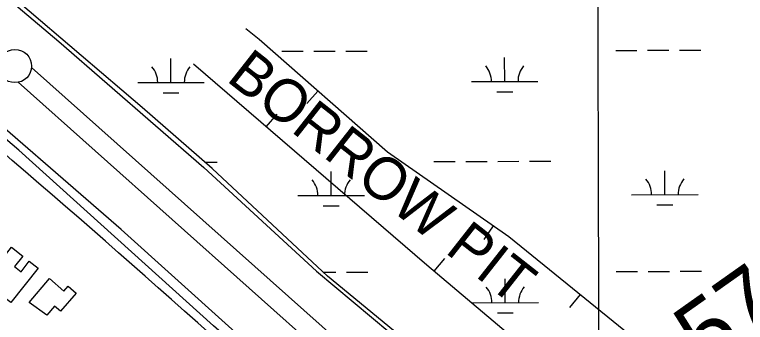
# Model space of a CAD drawing. Extents: x 3355724 to 3393621, y 594744 to 620174.
# Drawn here: x 3374730 to 3375830, y 615735 to 616199 of the extents above; entities that cross this region are included whole.
import ezdxf

# ---------------------------------------------------------------- set-up
doc = ezdxf.new("R2010")
doc.units = 0
for name, color, linetype in [('V-BLDG-OTLN', 7, 'Continuous'), ('V-BORW-IDEN', 7, 'Continuous'), ('V-BORW-LINE', 7, 'Continuous'), ('V-GRID-MAJR', 7, 'Continuous'), ('V-LEVE-TOET', 7, 'Continuous'), ('V-RIVR-EDGE', 7, 'Continuous'), ('V-ROAD-CNTR', 7, 'Continuous'), ('V-SURV-IDEN', 7, 'Continuous'), ('V-SURV-LINE', 7, 'Continuous'), ('V-TOPO-SHOR', 7, 'Continuous'), ('V-WETL-SWMP', 7, 'Continuous')]:
    doc.layers.add(name, color=color, linetype=linetype)

msp = doc.modelspace()

# ---------------------------------------------------------------- linework, layer by layer
at = {"layer": 'V-BLDG-OTLN'}
for points in [[(3374683.944, 615795.539), (3374725.869, 615848.711), (3374742.861, 615835.313), (3374730.401, 615819.511), (3374740.219, 615811.769), (3374752.575, 615827.439), (3374765.8310000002, 615816.986), (3374725, 615765.2000000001)], [(3374752.251, 615765.368), (3374783.188, 615801.282), (3374804.764, 615782.696), (3374811.002, 615789.942), (3374822.9250000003, 615779.671), (3374799.304, 615752.248), (3374790.313, 615759.9940000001), (3374778.7600000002, 615746.582)]]:
    msp.add_lwpolyline(points, close=True, dxfattribs=at)
at = {"layer": 'V-BORW-LINE'}
for p, q in [((3375186.619, 616083.447), (3375170.1180000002, 616064.666)), ((3375108.887, 616029.9379999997), (3375125.201, 616048.8809999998)), ((3375450.373, 615880.6759999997), (3375436.08, 615860.1649999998)), ((3375361.453, 615812.6079999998), (3375377.5840000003, 615831.7079999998)), ((3375580.949, 615777.3129999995), (3375565.188, 615757.9069999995))]:
    msp.add_line(p, q, dxfattribs=at)
msp.add_lwpolyline([(3374999.289, 616124.3249999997), (3375350.466, 615821.8869999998), (3375623.964, 615590.9099999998), (3375947.058, 615275.3879999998), (3376212.667, 615040.2929999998), (3376456.716, 614821.7659999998), (3376730.359, 614537.2219999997), (3376919.627, 614374.7149999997), (3376985.098, 614331.7339999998), (3377039.049, 614329.4969999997), (3377044.183, 614367.4619999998), (3376929.0330000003, 614512.7299999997), (3376763.9420000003, 614658.5999999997), (3376650.372, 614798.0959999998), (3376365.971, 615066.9819999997), (3376116.19, 615339.8889999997), (3375874.953, 615560.1719999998), (3375665.458, 615708.6739999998), (3375473.693, 615864.4269999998), (3375291.071, 615991.6769999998), (3375098.1550000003, 616161.1709999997), (3375078.477, 616177.2309999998)], dxfattribs=at)
at = {"layer": 'V-GRID-MAJR'}
msp.add_spline([(3375649.97, 600169.845), (3375634.111, 606227.569), (3375618.242, 612288.761), (3375602.373, 618349.974), (3375602.364, 618353.419)], degree=3, dxfattribs=at)
at = {"layer": 'V-LEVE-TOET'}
for points in [[(3375825.827, 615008.099), (3375822.0300000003, 615015.069), (3375811.421, 615025.452), (3375795.215, 615044.861), (3375673.98, 615158.795), (3375432.599, 615386.572), (3375213.561, 615584.466), (3374890.5870000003, 615875.407), (3374635.994, 616096.192), (3374322.151, 616352.343), (3373944.17, 616649.422), (3373708.889, 616836.304), (3373573.176, 616934.682), (3373207.762, 617215.082), (3372868.8510000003, 617474.657), (3372670.815, 617620.3910000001), (3372460.949, 617765.402), (3372217.63, 617927.042), (3371905.281, 618137.949), (3371607.651, 618305.732), (3371539.629639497, 618342.7830789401)], [(3374580.719, 616340.588), (3374797.119, 616158.1190000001), (3375014.911, 615968.7710000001), (3375184.477, 615812.333), (3375294.744, 615720.412), (3375421.562, 615609.273), (3375501.508, 615540.672), (3375591.798, 615461.088), (3375653.836, 615403.451), (3375709.619, 615348.512), (3375771.0100000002, 615272.302), (3375892.346, 615152.893)]]:
    msp.add_lwpolyline(points, dxfattribs=at)
at = {"layer": 'V-RIVR-EDGE'}
msp.add_spline([(3375380.8204065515, 618352.839487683), (3375420.269161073, 618323.7288901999), (3375445.0711899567, 618301.3690852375), (3375471.3372128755, 618279.7367578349), (3375501.2514702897, 618255.1710190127), (3375536.276148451, 618227.6682532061), (3375549.0314108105, 618211.9181147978), (3375559.9806337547, 618204.9456133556), (3375576.404016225, 618194.3040879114), (3375599.7519938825, 618175.2378175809), (3375638.7805102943, 618140.7797242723), (3375656.2815507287, 618122.4590093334), (3375673.4188523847, 618104.8702914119), (3375771.5203854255, 618011.4127710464), (3375800.3352914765, 617985.7531042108), (3375821.847401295, 617963.4014342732), (3375844.090604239, 617941.047956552), (3375861.608818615, 617929.6726263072), (3375882.3952586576, 617909.5160435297), (3375904.2557410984, 617880.2180850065), (3375960.4324058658, 617832.5578325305), (3375992.1536065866, 617799.5800033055), (3376041.0103011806, 617748.2823630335), (3376074.5510996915, 617712.0100952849), (3376185.4087989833, 617603.1679830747), (3376226.9789673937, 617561.7581778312), (3376338.574990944, 617455.8386303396), (3376381.9665649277, 617411.8654796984), (3376437.399482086, 617359.0893831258), (3376479.6935124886, 617314.7533975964), (3376500.101751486, 617289.4800668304), (3376531.4610212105, 617257.9653277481), (3376571.5708111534, 617217.2902311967), (3376620.047496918, 617160.1447498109), (3376637.9023333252, 617137.0710256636), (3376661.24307985, 617115.0803828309), (3376679.4806367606, 617098.9511394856), (3376697.7100586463, 617079.5319770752), (3376717.0316007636, 617058.2823701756), (3376731.600133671, 617036.6789673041), (3376745.4574590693, 617023.1193965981), (3376758.9483340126, 617009.1951832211), (3376794.6742768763, 616969.6275730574), (3376867.204724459, 616883.1787097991), (3376881.7859118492, 616866.6929588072), (3376901.8349315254, 616843.979357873), (3376931.3782190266, 616817.221243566), (3376968.555501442, 616773.2634590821), (3377038.169711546, 616690.1117460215), (3377066.9556930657, 616652.7545891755), (3377087.743037, 616632.9635529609), (3377103.0607408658, 616618.669273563), (3377120.9173850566, 616596.3266425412), (3377186.5087751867, 616512.4537791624), (3377216.026753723, 616475.460361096), (3377255.388276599, 616427.841687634), (3377303.854115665, 616366.3096474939), (3377369.4599680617, 616288.2855291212), (3377405.909772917, 616245.7917386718), (3377491.5239698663, 616128.6044240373), (3377526.120732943, 616075.8798492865), (3377552.7197623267, 616041.08694173), (3377626.701549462, 615950.2479041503), (3377654.399026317, 615916.1833780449), (3377678.450980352, 615886.1489030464), (3377699.9468201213, 615857.2173949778), (3377777.9152715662, 615752.4776452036), (3377803.0647691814, 615722.8060050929), (3377843.5301628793, 615678.1089924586), (3377867.953086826, 615650.2668929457), (3377881.43311507, 615631.9561208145), (3377905.4760301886, 615598.2661801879), (3377926.597284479, 615565.6801103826), (3377940.798463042, 615543.3465182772), (3377958.6496838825, 615518.8106078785), (3377971.761453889, 615499.4040999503), (3377982.683560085, 615481.4652016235), (3378059.551756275, 615375.2659772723), (3378094.520393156, 615325.0993245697), (3378126.935627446, 615277.1322784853), (3378185.172699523, 615175.7312579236), (3378207.005161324, 615135.1013559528), (3378307.8963870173, 614987.1701665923), (3378349.410514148, 614923.0964744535), (3378390.937295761, 614864.1404341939), (3378419.7223733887, 614826.4177307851), (3378449.2403519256, 614789.4243127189), (3378467.069879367, 614756.1152848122), (3378482.3496197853, 614726.4680497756), (3378509.64900998, 614679.2447512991), (3378546.0599474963, 614621.032458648), (3378577.3622720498, 614566.4882861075), (3378597.7298359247, 614524.765360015), (3378622.461361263, 614473.892923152), (3378650.120874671, 614424.4754414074), (3378694.902323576, 614351.2549501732), (3378714.9079564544, 614310.995114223), (3378749.113864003, 614248.0361396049), (3378759.6767508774, 614232.6569711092), (3378776.7914552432, 614205.9295891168), (3378791.6975140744, 614172.9933389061), (3378807.6947892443, 614137.8610976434), (3378844.8051836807, 614066.8528675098), (3378863.710561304, 614025.1335569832), (3378885.923935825, 613990.7170426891), (3378900.114267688, 613963.9968918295), (3378916.496071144, 613936.540224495), (3378929.245006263, 613918.2312601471), (3379005.705172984, 613794.8522512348), (3379023.1718655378, 613762.6407669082), (3379028.9934937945, 613751.6599077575), (3379038.0978099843, 613737.7465410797), (3379055.9707242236, 613721.9837481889), (3379063.2581542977, 613712.4614597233), (3379072.707227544, 613690.1396182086), (3379096.6931974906, 613633.4202441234), (3379107.597225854, 613608.1704145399), (3379127.6037626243, 613568.2761251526), (3379150.166413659, 613527.2788688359), (3379171.2840523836, 613493.2306127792), (3379216.0392884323, 613409.4092712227), (3379256.795205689, 613334.3709899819), (3379314.9789481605, 613211.4027222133), (3379346.2424053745, 613141.1400474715), (3379363.682885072, 613098.3277128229), (3379415.7174161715, 613001.6941637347), (3379435.348463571, 612957.7797660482), (3379449.5207176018, 612923.7486839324), (3379470.6184707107, 612881.6584034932), (3379540.480721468, 612750.9847333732), (3379564.8620664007, 612706.32749197), (3379589.606246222, 612660.5727069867), (3379652.216318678, 612553.6776412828), (3379662.3955811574, 612530.9884454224), (3379662.743049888, 612523.6766102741), (3379672.9403902, 612508.2983456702), (3379687.8600074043, 612480.845293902), (3379704.225540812, 612446.808788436), (3379704.944883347, 612442.0548753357), (3379706.0297724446, 612437.3000583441), (3379717.657662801, 612409.1240484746), (3379731.492390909, 612386.4258136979), (3379735.1243553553, 612376.9125641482), (3379746.0365187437, 612354.95265363), (3379762.0699495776, 612334.4422748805), (3379789.381090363, 612291.9710817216), (3379802.843040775, 612266.3493783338), (3379843.9645045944, 612191.3101932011), (3379872.705291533, 612135.6757082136), (3379896.3736211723, 612098.3312058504), (3379901.453309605, 612082.9655957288), (3379906.5013618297, 612054.8058559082), (3379909.405848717, 612046.7566003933), (3379918.87571147, 612032.8423298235), (3379935.2764966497, 612013.0621403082), (3379944.727377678, 611991.4713919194), (3379953.4327033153, 611964.0337063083), (3379958.889688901, 611953.4192976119), (3379967.2791820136, 611946.0875768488), (3379978.563219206, 611926.6855883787), (3379993.4846441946, 611899.963629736), (3380009.5054205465, 611874.3355991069), (3380070.2678745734, 611759.4030284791), (3380080.7991252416, 611731.2297302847), (3380088.0657658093, 611713.2998708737), (3380095.703376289, 611697.5623869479), (3380112.460669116, 611674.1258279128), (3380124.8341148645, 611651.7967552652), (3380123.721205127, 611645.219628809), (3380124.7934397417, 611635.3471599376), (3380137.1605582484, 611610.4592613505), (3380148.81375757, 611592.5185552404), (3380155.016298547, 611587.7510837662), (3380167.036852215, 611570.54056689), (3380177.5780456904, 611546.3882808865), (3380195.7758313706, 611514.1749887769), (3380214.7083257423, 611483.4220751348), (3380224.5346961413, 611465.8514350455), (3380228.1494866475, 611449.3928008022), (3380233.5911060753, 611432.5641005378), (3380253.971324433, 611395.9588263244), (3380276.5195132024, 611349.1128250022), (3380293.9599928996, 611306.3004903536), (3380320.89293264, 611258.7125492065), (3380341.2794782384, 611224.6661009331), (3380352.568938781, 611207.4573918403), (3380364.603954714, 611196.0956199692), (3380367.1419911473, 611187.6817217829), (3380368.9498383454, 611179.6351779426), (3380378.4215088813, 611166.4520004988), (3380388.9952424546, 611155.4593907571), (3380388.981684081, 611149.9761923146), (3380391.1424233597, 611136.8110927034), (3380399.1446765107, 611120.707158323), (3380419.9039998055, 611089.5841786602), (3380436.6793704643, 611073.4585508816), (3380444.3296354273, 611062.8387188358), (3380443.954146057, 611058.8186105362), (3380442.8430441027, 611052.9725772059), (3380446.478624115, 611044.9215139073), (3380459.9568445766, 611025.8796486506), (3380464.3063437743, 611010.8813928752), (3380471.205629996, 610992.2213442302), (3380486.474523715, 610958.1875504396), (3380519.26163181, 610912.7784264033), (3380526.8847800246, 610891.1921974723), (3380537.404280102, 610858.266793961), (3380551.572918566, 610822.7735255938), (3380593.77204035, 610740.0551509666), (3380615.2389555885, 610699.4261528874), (3380640.7386336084, 610663.5393173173), (3380652.3836979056, 610642.3086921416), (3380663.6487533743, 610615.2302258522), (3380668.0009642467, 610601.3286097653), (3380674.1890429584, 610590.712393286), (3380692.0619571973, 610574.9496003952), (3380702.632075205, 610562.4948044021), (3380712.4557339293, 610543.8275246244), (3380727.724627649, 610509.7937308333), (3380735.3468719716, 610487.8419553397), (3380741.1422873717, 610466.2602458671), (3380745.881738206, 610461.1308433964), (3380752.8153723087, 610456.3615641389), (3380760.4656372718, 610445.7417320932), (3380779.7492159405, 610409.1391695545), (3380795.7519144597, 610376.200207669), (3380801.586197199, 610370.337000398), (3380807.424999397, 610366.3015259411), (3380811.785345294, 610355.6898289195), (3380812.48841778, 610344.3560776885), (3380817.937268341, 610330.4517499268), (3380829.2267288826, 610313.2430408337), (3380839.048579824, 610293.8446679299), (3380846.348664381, 610289.4400313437), (3380854.008872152, 610282.8412114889), (3380859.103926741, 610273.6898929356), (3380867.0971409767, 610253.9304929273), (3380868.5484805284, 610249.5403186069), (3380877.662739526, 610239.6479641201), (3380887.12808282, 610223.9059607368), (3380896.594330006, 610208.529503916), (3380899.848997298, 610194.265052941), (3380899.839054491, 610190.2440407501), (3380906.0497304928, 610188.7664883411), (3380912.98607627, 610185.0938487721), (3380918.449389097, 610177.0382660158), (3380918.434926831, 610171.1895210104), (3380918.4186567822, 610164.6096828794), (3380918.4014828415, 610157.6642981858), (3380926.0634983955, 610151.7965714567), (3380935.5405922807, 610140.80667339), (3380947.1838487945, 610118.8449550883), (3380956.2854533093, 610103.8349487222), (3380965.0359735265, 610094.6745912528), (3380973.404677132, 610078.9352995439), (3380975.210716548, 610070.1576625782), (3380981.770669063, 610062.0993681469), (3380992.7144686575, 610052.9335873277), (3380996.7155952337, 610044.8816201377), (3380999.973878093, 610032.0793554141), (3380999.951280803, 610022.9406913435), (3381003.216794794, 610013.0627991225), (3381010.1468133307, 610006.8313336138), (3381018.9063724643, 610001.3264417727), (3381025.8273520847, 609991.4395106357), (3381035.295407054, 609976.7941469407), (3381052.049988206, 609952.2609482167), (3381064.0642146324, 609932.4916054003), (3381081.1689761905, 609901.7432112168), (3381081.1445711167, 609891.8734540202), (3381086.5807671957, 609872.8514743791), (3381093.837464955, 609850.900602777), (3381104.0221507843, 609830.4046862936), (3381125.493585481, 609791.6034210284), (3381152.4418913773, 609750.2297714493), (3381171.0196858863, 609723.8643204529), (3381189.573979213, 609687.9946588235), (3381212.133918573, 609645.9007628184), (3381231.427440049, 609613.3192124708), (3381244.142931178, 609581.4850252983), (3381257.9387919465, 609543.0682883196), (3381275.036322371, 609509.395521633), (3381303.062286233, 609460.3426825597), (3381339.808037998, 609389.7009028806), (3381375.859756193, 609334.0483400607), (3381398.434157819, 609297.8031890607), (3381410.8103152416, 609276.5707561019), (3381420.3027752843, 609271.7951496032), (3381423.218108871, 609268.132452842), (3381426.1262113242, 609261.545383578), (3381429.776253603, 609259.343065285), (3381434.8920976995, 609258.5993176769), (3381439.6387796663, 609256.394287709), (3381499.3398457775, 609155.7207447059), (3381528.0752093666, 609097.8929803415), (3381535.3545044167, 609085.08077281), (3381535.3346188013, 609077.0387484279), (3381535.3056942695, 609065.3412584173), (3381535.287616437, 609058.0303271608), (3381541.1255147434, 609053.6293061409), (3381551.713710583, 609048.4854414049), (3381554.98193625, 609039.7041888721), (3381564.0735979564, 609020.6731703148), (3381586.268894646, 608978.9457247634), (3381604.8258996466, 608944.1727028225), (3381620.107447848, 608915.2565609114), (3381628.486094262, 608903.5382813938), (3381636.8810107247, 608898.3998400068), (3381651.07857372, 608874.60406165), (3381663.082857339, 608850.8137066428), (3381678.3824833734, 608829.2084959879), (3381690.774910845, 608814.5559011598), (3381704.606023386, 608790.3954801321), (3381708.222621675, 608774.6679390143), (3381710.374322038, 608757.8473737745), (3381710.3517247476, 608748.7087097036), (3381708.496875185, 608737.7468322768), (3381708.117770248, 608732.264537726), (3381711.372437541, 608718.000086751), (3381715.707474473, 608697.1530859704), (3381717.882676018, 608689.836731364), (3381723.33785382, 608678.4912295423), (3381733.5315785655, 608661.650778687), (3381741.560948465, 608656.5132411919), (3381747.0342041, 608652.4786706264), (3381752.8721024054, 608648.077649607), (3381759.8174870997, 608648.0604756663), (3381763.4702410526, 608646.9547970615), (3381765.648154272, 608640.7350821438), (3381769.2855420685, 608633.4151119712), (3381776.2137528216, 608626.4525533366), (3381784.6177082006, 608624.9695775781), (3381791.560381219, 608623.8557639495), (3381802.134114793, 608612.8631542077), (3381808.334847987, 608607.3645896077), (3381820.722756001, 608590.8842619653), (3381831.6692672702, 608582.8151208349), (3381840.7826223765, 608572.5572197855), (3381857.5118945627, 608537.7887173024), (3381870.222866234, 608504.1267973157), (3381876.0155699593, 608481.4484481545), (3381884.748012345, 608464.9771594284), (3381898.5872599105, 608444.1066574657), (3381913.540321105, 608430.1788285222), (3381932.090094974, 608392.4814340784), (3381960.8317858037, 608337.2124956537), (3381973.560835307, 608310.8615069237), (3381973.5517963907, 608307.2060412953), (3381972.802625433, 608299.8969178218), (3381972.790874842, 608295.144812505), (3381974.966076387, 608287.8284578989), (3381977.8768905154, 608282.3380283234), (3381985.906260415, 608277.2004908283), (3381990.2774530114, 608270.9753525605), (3381997.1939131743, 608259.2606886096), (3382005.925451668, 608242.4238533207), (3382015.7427831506, 608221.1977476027), (3382031.0261391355, 608193.0126988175), (3382044.491705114, 608168.8531816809), (3382063.0487101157, 608134.0801597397), (3382080.1326821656, 608094.9241946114), (3382096.4936961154, 608059.0599563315), (3382116.8594522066, 608016.6059371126), (3382135.0545262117, 607983.2960053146), (3382154.3344893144, 607945.231256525), (3382180.5173542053, 607889.9686453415), (3382186.330847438, 607875.6978671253), (3382201.587990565, 607836.9119680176), (3382211.0036198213, 607801.0649036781), (3382218.988699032, 607778.0155846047), (3382226.2725135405, 607767.0311098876), (3382233.5581358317, 607756.777728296), (3382247.730389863, 607722.7466461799), (3382259.0017725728, 607698.22700583), (3382261.536193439, 607688.3509213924), (3382266.620401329, 607674.813044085), (3382270.996113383, 607670.4156386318), (3382277.9143813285, 607659.4320678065), (3382286.289412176, 607646.2516020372), (3382288.8247369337, 607636.7410641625), (3382293.537974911, 607621.0108113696), (3382300.433645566, 607600.8885764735), (3382310.614715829, 607578.9304737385), (3382319.7208398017, 607565.7482001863), (3382337.926760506, 607536.8248271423), (3382350.3047257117, 607516.3234873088), (3382357.5731740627, 607499.1247210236), (3382366.3038086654, 607481.9223391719), (3382374.3151007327, 607469.47387042), (3382380.8813804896, 607463.9744019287), (3382386.728317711, 607463.2288465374), (3382390.7493299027, 607463.2189037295), (3382394.3966605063, 607459.9199457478), (3382404.9459890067, 607439.05757881), (3382412.575464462, 607420.0301758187), (3382419.0947418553, 607395.5222860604), (3382431.8147524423, 607365.5158317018), (3382444.5383785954, 607336.9715635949), (3382461.276689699, 607305.8585267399), (3382481.643349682, 607263.7700540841), (3382528.251627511, 607190.1794968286), (3382546.8239986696, 607161.6207664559), (3382558.102612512, 607140.0254986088), (3382565.367445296, 607121.3645460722), (3382577.7408910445, 607099.0354734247), (3382593.75262848, 607069.7519771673), (3382609.407858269, 607044.1248504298), (3382624.339226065, 607021.4239039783), (3382632.3559414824, 607011.1687146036), (3382645.4830776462, 606997.9764982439), (3382659.346730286, 606986.9757534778), (3382671.3745150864, 606972.6896091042), (3382685.2137626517, 606951.8191071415)], degree=3, dxfattribs=at)
at = {"layer": 'V-ROAD-CNTR'}
msp.add_arc((3363183.3422084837, 602512.5921495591), 17736.984324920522, 47.255929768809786, 52.738199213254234, dxfattribs=at)
at = {"layer": 'V-SURV-LINE'}
for points in [[(3374755.8775742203, 616119.1017014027), (3375450.728777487, 615499.5225454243)], [(3375430.7478398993, 615477.1448210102), (3374735.8971279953, 616096.7235388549)]]:
    msp.add_lwpolyline(points, dxfattribs=at)
msp.add_circle((3374730.96979, 616121.2137899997), 25, dxfattribs=at)
at = {"layer": 'V-TOPO-SHOR'}
msp.add_lwpolyline([(3375787.411, 615027.406), (3375610.893, 615199.671), (3375326.404, 615471.1460000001), (3375029.511, 615730.1630000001), (3374736.75, 615994.711), (3374423.2600000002, 616261.287), (3374143.719, 616483.735), (3373867.642, 616700.667), (3373729.957, 616805.334)], dxfattribs=at)
at = {"layer": 'V-WETL-SWMP'}
for p, q in [((3374922.4091544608, 616058.8351043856), (3374738.8131621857, 616215.5741096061)), ((3375132.6163516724, 616143.4219853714), (3375164.616240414, 616143.5057610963)), ((3375180.6161847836, 616143.5476489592), (3375212.6160735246, 616143.6314246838)), ((3375228.616017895, 616143.6733125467), (3375260.6159066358, 616143.7570882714)), ((3375634.5226066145, 616144.7359762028), (3375666.5224953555, 616144.8197519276)), ((3375682.522439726, 616144.8616397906), (3375714.522328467, 616144.9454155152)), ((3375730.5222728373, 616144.9873033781), (3375762.5221615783, 616145.0710791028)), ((3374965.6744889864, 616096.5547734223), (3374965.580238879, 616132.554649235)), ((3375467.580743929, 616097.8687642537), (3375467.4864938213, 616133.8686400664)), ((3374915.6746628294, 616096.423873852), (3375015.674315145, 616096.6856729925)), ((3375417.5809177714, 616097.7378646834), (3375517.5805700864, 616097.9996638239)), ((3374953.7149299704, 616081.0924107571), (3374977.714846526, 616081.1552425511)), ((3375455.621184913, 616082.4064015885), (3375479.6211014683, 616082.4692333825)), ((3375027.620150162, 615967.1141014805), (3374922.4091544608, 616058.8351043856)), ((3375016.7195988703, 615976.6170007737), (3375035.1446014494, 615976.6652374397)), ((3375361.051468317, 615977.5184617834), (3375393.0513570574, 615977.6022375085)), ((3375409.0513014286, 615977.6441253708), (3375441.0511901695, 615977.7279010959)), ((3375457.05113454, 615977.7697889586), (3375489.0510232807, 615977.8535646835)), ((3375505.050967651, 615977.8954525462), (3375537.050856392, 615977.979228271)), ((3375200.9351438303, 615804.8620972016), (3375027.620150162, 615967.1141014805)), ((3375206.5928513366, 615926.3719162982), (3375206.498601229, 615962.3717921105)), ((3375708.4991062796, 615927.6859071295), (3375708.4048561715, 615963.6857829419)), ((3375156.593025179, 615926.2410167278), (3375256.5926774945, 615926.5028158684)), ((3375658.499280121, 615927.5550075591), (3375758.498932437, 615927.8168066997)), ((3375194.63329232, 615910.909553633), (3375218.6332088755, 615910.972385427)), ((3375696.5395472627, 615912.2235444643), (3375720.539463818, 615912.2863762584)), ((3375194.477215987, 615810.9078045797), (3375213.4870361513, 615810.9575722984)), ((3375229.4869805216, 615810.9994601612), (3375261.486869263, 615811.0832358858)), ((3375635.3935692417, 615812.0621238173), (3375667.393457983, 615812.1458995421)), ((3375683.393402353, 615812.187787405), (3375715.393291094, 615812.2715631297)), ((3375731.393235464, 615812.3134509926), (3375763.393124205, 615812.3972267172)), ((3375384.517135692, 615654.3000917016), (3375200.9351438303, 615804.8620972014)), ((3375468.451706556, 615765.1949118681), (3375468.3574564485, 615801.1947876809)), ((3375418.4518803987, 615765.0640122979), (3375518.451532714, 615765.3258114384)), ((3375456.4921475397, 615749.732549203), (3375480.492064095, 615749.795380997))]:
    msp.add_line(p, q, dxfattribs=at)
for centre, radius, start, end in [((3374910.430501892, 616096.8849494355), 35.24628790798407, 359.3781799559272, 40.921838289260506), ((3375020.915989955, 616097.1742004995), 35.246287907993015, 139.378176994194, 180.92183532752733), ((3375412.336756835, 616098.1989402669), 35.24628790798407, 359.3781799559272, 40.921838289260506), ((3375522.8222448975, 616098.4881913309), 35.246287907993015, 139.378176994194, 180.92183532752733), ((3375151.348864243, 615926.7020923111), 35.24628790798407, 359.3781799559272, 40.921838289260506), ((3375261.8343523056, 615926.9913433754), 35.246287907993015, 139.378176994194, 180.92183532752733), ((3375653.2551191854, 615928.0160831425), 35.24628790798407, 359.3781799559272, 40.921838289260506), ((3375763.740607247, 615928.3053342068), 35.246287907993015, 139.378176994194, 180.92183532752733), ((3375413.2077194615, 615765.5250878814), 35.24628790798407, 359.3781799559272, 40.921838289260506), ((3375523.6932075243, 615765.8143389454), 35.246287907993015, 139.378176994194, 180.92183532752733)]:
    msp.add_arc(centre, radius, start, end, dxfattribs=at)

# ---------------------------------------------------------------- texts
at = {"layer": 'V-BORW-IDEN'}
msp.add_text('BORROW PIT', height=63.999873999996, rotation=321.8288281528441, dxfattribs=at).set_placement((3375047.205022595, 616100.0521395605))
at = {"layer": 'V-SURV-IDEN'}
msp.add_text('5723+07.0', height=99.99999999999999, rotation=35.266150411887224, dxfattribs=at).set_placement((3375770.063763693, 615661.0507046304))

doc.saveas('drawing.dxf')
